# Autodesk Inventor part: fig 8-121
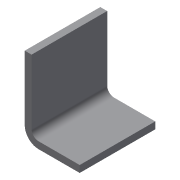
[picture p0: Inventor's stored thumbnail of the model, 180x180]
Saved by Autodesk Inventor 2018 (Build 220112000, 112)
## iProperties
Created: 2009-09
Part Number: fig 8-121
Document SubType Name: Modeling
Designer: Sham
Density: 1 g/cm^3
Material: Generic
Appearance: Default
Author: Sham
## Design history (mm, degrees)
sketch "Sketch1"
  geometry: L1 (-33.976, 22)-(0, 22); L2 (0, 22)-(0, 0); L3 (0, 0)-(-33.976, 0); L4 (-33.976, 0)-(-33.976, 22)
  constraints: 8 end point, 2 parallel, 1 horizontal, 1 perpendicular
extrude "Extrusion1" new body sketch "Sketch1" distance "d0" = 2; taper "d1" = 0 deg
sketch "Sketch2"
  geometry: L1 (-12, 22)-(-12, 0)
  constraints: 2 end point
feature "Bend Part1" sketch "Sketch2" dims "d5" = 90 deg, "d6" = 2
body "Solid1"
